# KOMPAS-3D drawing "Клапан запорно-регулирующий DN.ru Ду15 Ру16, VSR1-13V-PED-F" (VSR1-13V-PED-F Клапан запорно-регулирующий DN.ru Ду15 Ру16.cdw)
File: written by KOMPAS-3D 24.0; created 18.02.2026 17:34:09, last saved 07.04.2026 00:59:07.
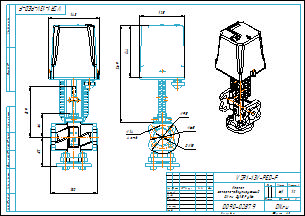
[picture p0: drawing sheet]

Document properties: Автор: R2D2; Форматы листов документа: A3; Полное имя файла: VSR1-13V-PED-F Клапан запорно-регулирующий DN.ru Ду15 Ру16.m3d; Масса: 6.1; Наименование: Клапан запорно-регулирующий DN.ru Ду15 Ру16; Количество листов документа: 1; Примечание: D090-02879

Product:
- Part/product: Клапан запорно-регулирующий DN.ru Ду15 Ру16  | designation VSR1-13V-PED-F
    Масса: 6.1
    Раздел спецификации: Прочие изделия
    Примечание: D090-02879

Views: Вид 1, Спереди
Referenced files in E:\Работа\Зайцев\Солянка\VSR1-13V-PED-F Клапан запорно-регулирующий DN.ru\DN15\DN15 Kv0.16\: VSR1-13V-PED-F Клапан запорно-регулирующий DN.ru Ду15 Ру16.m3d
Referenced files in E:\Работа\Зайцев\Для компаса\: чертеж DN.ru А3.cdt
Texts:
  Линейный размер
  VSR1-13V-PED-F
  чертеж DN.ru А3.cdt
  Клапан
  запорно-регулирующий
  DN.ru Ду15 Ру16
  Клапан запорно-регулирующий DN.ru Ду15 Ру16
  VSR1-13V-PED-F Клапан запорно-регулирующий DN.ru Ду15 Ру16
Dimensions and other numbers on the sheet: 0; 3; 2; 4; 130; 82; 143; 64; 139; 1:2; 1; 6,1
